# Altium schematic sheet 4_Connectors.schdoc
size 309 x 223 mm; Symbol: Artery_A4; Device: Artery_A4; Company: Artery Technology; Drawed: SD; Version: 1.2; Page Size: A4; @Project Name: AT_START_F421_V1.2; @Page Count: 4; @Update Date: 2023-09-01; @Schematic Name: AT_START_F421; @Page No: 4; @Page Name: Connectors
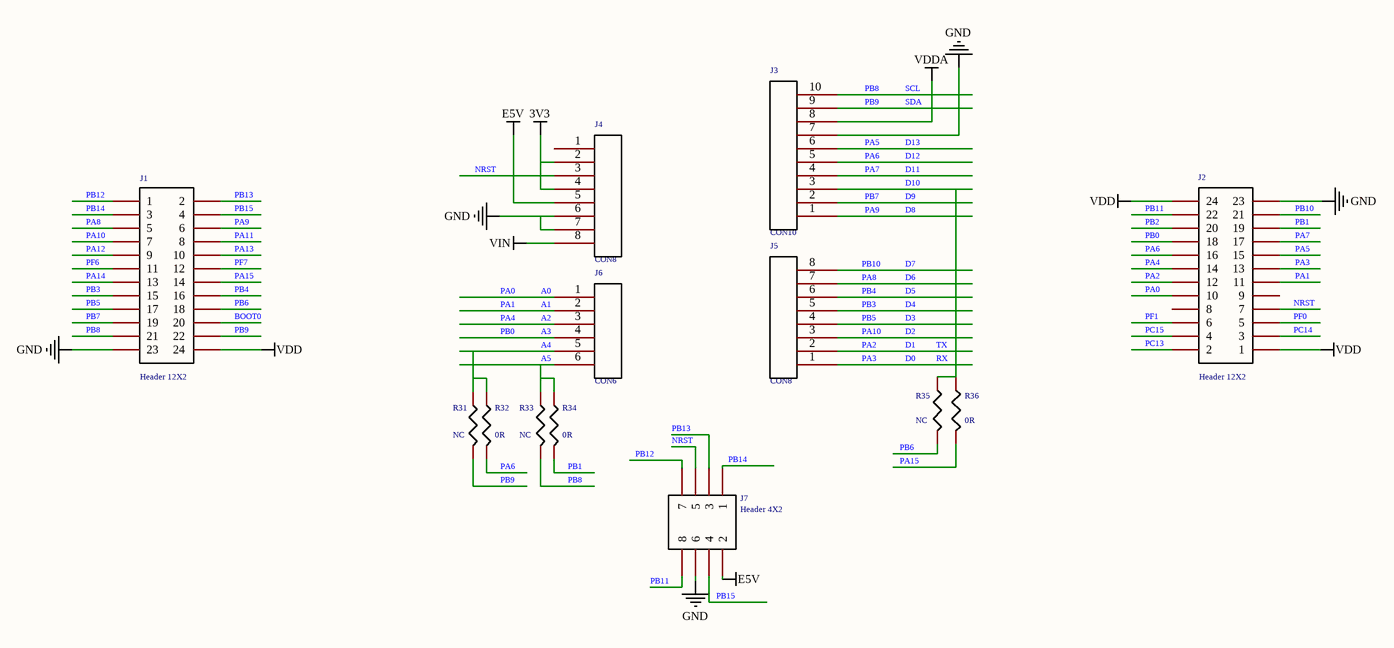
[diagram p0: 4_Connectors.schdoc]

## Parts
J1  Header 12X2  [HEAD2*12]
J2  Header 12X2  [HEAD2*12]
J3  CON10  [HDR1X10 - 2#]
J4  CON8  [HDR1X8 - 2#]
J5  CON8  [HDR1X8 - 2#]
J6  CON6  [HDR1X6 -2#]
J7  Header 4X2  [HDR2X4]
R31  NC  [SB-PAD]
R32  0R  [SB-PAD]
R33  NC  [SB-PAD]
R34  0R  [SB-PAD]
R35  NC  [SB-PAD]
R36  0R  [SB-PAD]

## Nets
3V3: J4.2 J4.4
E5V: J4.5 J7.2
GND: J1.23 J2.23 J3.7 J4.6 J4.7 J7.6
VDD: J1.24 J2.1 J2.24
VDDA: J3.8
VIN: J4.8
A0: J2.10 J6.1  [also labelled PA0]
A1: J2.11 J6.2  [also labelled PA1]
A2: J2.14 J6.3  [also labelled PA4]
A3: J2.18 J6.4  [also labelled PB0]
A4: J6.5 R31.1 R32.1
A5: J6.6 R33.1 R34.1
BOOT0: J1.20
D0: J2.13 J5.1  [also labelled PA3, RX]
D1: J2.12 J5.2  [also labelled PA2, TX]
D2: J1.7 J5.3  [also labelled PA10]
D3: J1.17 J5.4  [also labelled PB5]
D4: J1.15 J5.5  [also labelled PB3]
D5: J1.16 J5.6  [also labelled PB4]
D6: J1.5 J5.7  [also labelled PA8]
D7: J2.21 J5.8  [also labelled PB10]
D8: J1.6 J3.1  [also labelled PA9]
D9: J1.19 J3.2  [also labelled PB7]
D10: J3.3 R35.1 R36.1
D11: J2.17 J3.4  [also labelled PA7]
D12: J2.16 J3.5 R32.2  [also labelled PA6]
D13: J2.15 J3.6  [also labelled PA5]
NRST: J2.7 J4.3 J7.5
PA11: J1.8
PA12: J1.9
PA13: J1.10
PA14: J1.13
PA15: J1.14 R36.2
PB1: J2.19 R34.2
PB2: J2.20
PB6: J1.18 R35.2
PB8: J1.21 J3.10 R33.2  [also labelled SCL]
PB9: J1.22 J3.9 R31.2  [also labelled SDA]
PB11: J2.22 J7.8
PB12: J1.1 J7.7
PB13: J1.2 J7.3
PB14: J1.3 J7.1
PB15: J1.4 J7.4
PC13: J2.2
PC14: J2.3
PC15: J2.4
PF0: J2.5
PF1: J2.6
PF6: J1.11
PF7: J1.12

Not connected (* = marked no-connect by the designer): J2 8 9; J4 1

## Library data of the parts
J1 J2 = Header 12X2: 双排直插排针2*12P 2.54mm(黑色); Add into BOM: yes
J3 = CON10: 单排直插排母1*10P 2.54mm(黄色); Symbol: CON10_0; Add into BOM: yes
J4 J5 = CON8: 单排直插排母1*8P 2.54mm(黄色); Add into BOM: yes
J6 = CON6: 单排直插排母1*6P 2.54mm(黄色); Add into BOM: yes
J7 = Header 4X2: 双排直插针2*4P 2.54mm(黄色); Add into BOM: yes
R31 R33 R35 = NC: 贴片电阻0R,1/10W,5%,0603; Symbol: 10K,1/10W,1%,SMD0603_Dup1; Add into BOM: yes
R32 R34 R36 = 0R: 贴片电阻0R,1/10W,5%,0603; Symbol: 10K,1/10W,1%,SMD0603_Dup1; Add into BOM: yes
